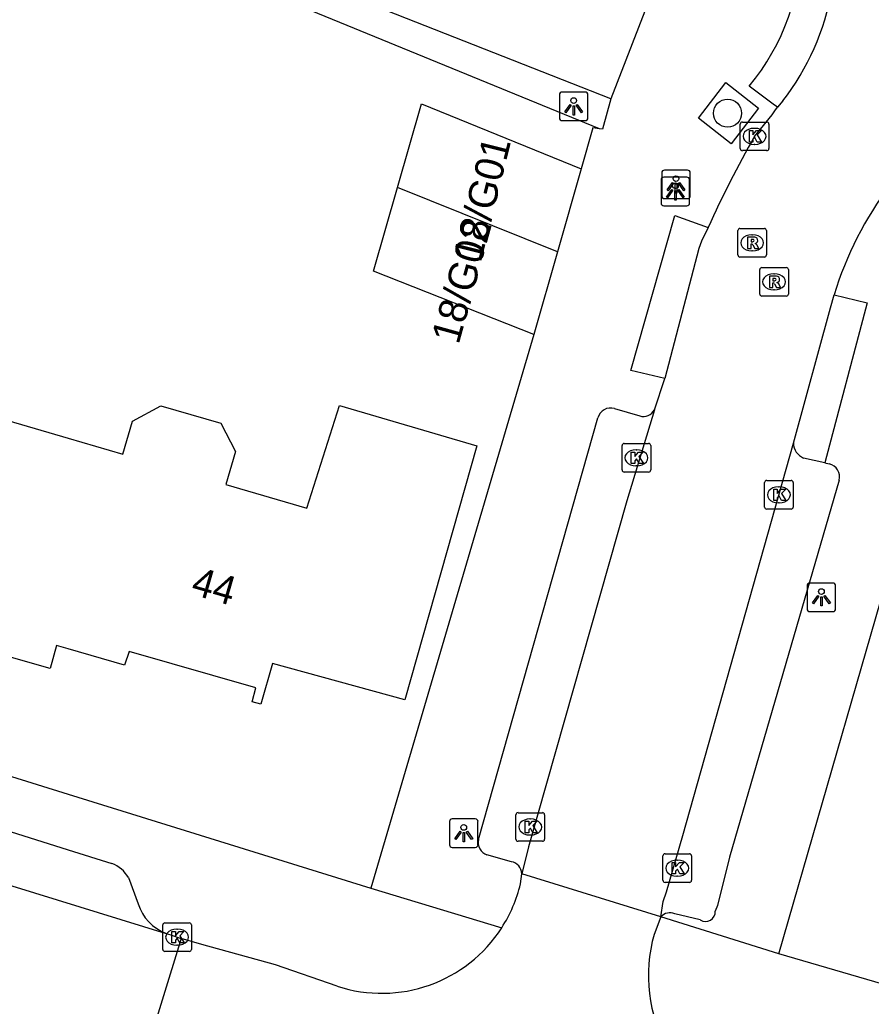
# Model space of a CAD drawing. Extents: x 159718 to 160783, y 383290 to 384030.
# Drawn here: x 159998.31 to 160028.05, y 383507.63 to 383542.1 of the extents above; entities that cross this region are included whole.
import ezdxf

# ---------------------------------------------------------------- set-up
doc = ezdxf.new("R2010")
doc.units = 0
for name, color, linetype in [('IMGEO_Boom', 7, 'Continuous'), ('IMGEO_Hek', 7, 'Continuous'), ('IMGEO_Kolk', 7, 'Continuous'), ('IMGEO_Lichtpunt', 7, 'Continuous'), ('IMGEO_Muur', 7, 'Continuous'), ('IMGEO_Pand', 7, 'Continuous'), ('IMGEO_Pand_nummerreeks', 7, 'Continuous'), ('IMGEO_Parkeervlak_open', 7, 'Continuous'), ('IMGEO_Rijbaan_lokaal_open', 7, 'Continuous'), ('IMGEO_Rioolput', 7, 'Continuous'), ('IMGEO_Voetpad_open', 7, 'Continuous')]:
    doc.layers.add(name, color=color, linetype=linetype)

msp = doc.modelspace()

# ---------------------------------------------------------------- linework, layer by layer
at = {"layer": 'IMGEO_Boom'}
msp.add_circle((160023.032, 383538.831), 0.489, dxfattribs=at)
at = {"layer": 'IMGEO_Hek'}
msp.add_lwpolyline([(160018.559, 383538.287), (160004.082, 383544.224), (160006.109, 383549.395), (160000, 383551.763)], dxfattribs=at)
at = {"layer": 'IMGEO_Kolk'}
for p, q in [((160023.475, 383537.597), (160023.475, 383538.449)), ((160023.55, 383538.523), (160024.402, 383538.523)), ((160024.476, 383538.449), (160024.476, 383537.597)), ((160023.963, 383538.303), (160023.988, 383538.303)), ((160024.402, 383537.523), (160023.55, 383537.523)), ((160023.986, 383537.743), (160023.961, 383537.743)), ((160019.347, 383526.368), (160019.347, 383527.22)), ((160019.422, 383527.294), (160020.274, 383527.294)), ((160020.348, 383527.22), (160020.348, 383526.368)), ((160019.835, 383527.074), (160019.86, 383527.074)), ((160019.858, 383526.514), (160019.833, 383526.514)), ((160020.274, 383526.294), (160019.422, 383526.294)), ((160024.325, 383525.074), (160024.325, 383525.926)), ((160024.4, 383526), (160025.252, 383526)), ((160024.813, 383525.78), (160024.838, 383525.78)), ((160025.326, 383525.926), (160025.326, 383525.074)), ((160024.836, 383525.22), (160024.811, 383525.22)), ((160025.252, 383525), (160024.4, 383525)), ((160015.716, 383514.395), (160016.568, 383514.395)), ((160015.641, 383513.469), (160015.641, 383514.321)), ((160016.129, 383514.175), (160016.154, 383514.175)), ((160016.642, 383514.321), (160016.642, 383513.469)), ((160016.568, 383513.395), (160015.716, 383513.395)), ((160016.152, 383513.615), (160016.127, 383513.615)), ((160020.85, 383512.958), (160021.702, 383512.958)), ((160020.775, 383512.032), (160020.775, 383512.884)), ((160021.263, 383512.738), (160021.288, 383512.738)), ((160021.776, 383512.884), (160021.776, 383512.032)), ((160021.702, 383511.958), (160020.85, 383511.958)), ((160021.286, 383512.178), (160021.261, 383512.178)), ((160003.379, 383510.546), (160004.231, 383510.546)), ((160003.304, 383509.62), (160003.304, 383510.472)), ((160003.792, 383510.326), (160003.817, 383510.326)), ((160004.305, 383510.472), (160004.305, 383509.62)), ((160004.231, 383509.546), (160003.379, 383509.546)), ((160003.815, 383509.766), (160003.79, 383509.766))]:
    msp.add_line(p, q, dxfattribs=at)
for points in [[(160023.475, 383537.597), (160023.475, 383538.449)], [(160023.55, 383538.523), (160024.402, 383538.523)], [(160024.476, 383538.449), (160024.476, 383537.597)], [(160023.796, 383538.223), (160023.919, 383538.223), (160023.919, 383538.072), (160024.049, 383538.223), (160024.213, 383538.223), (160024.067, 383538.072), (160024.22, 383537.823), (160024.068, 383537.823), (160023.983, 383537.987), (160023.919, 383537.92), (160023.919, 383537.823), (160023.796, 383537.823), (160023.796, 383538.223)], [(160024.402, 383537.523), (160023.55, 383537.523)], [(160019.347, 383526.368), (160019.347, 383527.22)], [(160019.422, 383527.294), (160020.274, 383527.294)], [(160020.348, 383527.22), (160020.348, 383526.368)], [(160019.668, 383526.994), (160019.791, 383526.994), (160019.791, 383526.843), (160019.921, 383526.994), (160020.085, 383526.994), (160019.939, 383526.843), (160020.092, 383526.594), (160019.94, 383526.594), (160019.855, 383526.758), (160019.791, 383526.691), (160019.791, 383526.594), (160019.668, 383526.594), (160019.668, 383526.994)], [(160020.274, 383526.294), (160019.422, 383526.294)], [(160024.325, 383525.074), (160024.325, 383525.926)], [(160024.4, 383526), (160025.252, 383526)], [(160024.646, 383525.7), (160024.769, 383525.7), (160024.769, 383525.549), (160024.899, 383525.7), (160025.063, 383525.7), (160024.917, 383525.549), (160025.07, 383525.3), (160024.918, 383525.3), (160024.833, 383525.464), (160024.769, 383525.397), (160024.769, 383525.3), (160024.646, 383525.3), (160024.646, 383525.7)], [(160025.326, 383525.926), (160025.326, 383525.074)], [(160025.252, 383525), (160024.4, 383525)], [(160015.716, 383514.395), (160016.568, 383514.395)], [(160015.641, 383513.469), (160015.641, 383514.321)], [(160015.962, 383514.095), (160016.085, 383514.095), (160016.085, 383513.944), (160016.215, 383514.095), (160016.379, 383514.095), (160016.233, 383513.944), (160016.386, 383513.695), (160016.234, 383513.695), (160016.149, 383513.859), (160016.085, 383513.792), (160016.085, 383513.695), (160015.962, 383513.695), (160015.962, 383514.095)], [(160016.642, 383514.321), (160016.642, 383513.469)], [(160016.568, 383513.395), (160015.716, 383513.395)], [(160020.85, 383512.958), (160021.702, 383512.958)], [(160020.775, 383512.032), (160020.775, 383512.884)], [(160021.096, 383512.658), (160021.219, 383512.658), (160021.219, 383512.507), (160021.349, 383512.658), (160021.513, 383512.658), (160021.367, 383512.507), (160021.52, 383512.258), (160021.368, 383512.258), (160021.283, 383512.422), (160021.219, 383512.355), (160021.219, 383512.258), (160021.096, 383512.258), (160021.096, 383512.658)], [(160021.776, 383512.884), (160021.776, 383512.032)], [(160021.702, 383511.958), (160020.85, 383511.958)], [(160003.379, 383510.546), (160004.231, 383510.546)], [(160003.304, 383509.62), (160003.304, 383510.472)], [(160003.625, 383510.246), (160003.748, 383510.246), (160003.748, 383510.095), (160003.878, 383510.246), (160004.042, 383510.246), (160003.896, 383510.095), (160004.049, 383509.846), (160003.897, 383509.846), (160003.812, 383510.01), (160003.748, 383509.943), (160003.748, 383509.846), (160003.625, 383509.846), (160003.625, 383510.246)], [(160004.305, 383510.472), (160004.305, 383509.62)], [(160004.231, 383509.546), (160003.379, 383509.546)]]:
    msp.add_lwpolyline(points, dxfattribs=at)
for centre, start, end in [((160023.552, 383538.447), 91.552, 178.448), ((160023.552, 383538.447), 91.552, 178.448), ((160024.4, 383538.447), 1.552, 88.448), ((160024.4, 383538.447), 1.552, 88.448), ((160023.552, 383537.599), 181.552, 268.448), ((160023.552, 383537.599), 181.552, 268.448), ((160024.4, 383537.599), 271.552, 358.448), ((160024.4, 383537.599), 271.552, 358.448), ((160019.424, 383527.218), 91.552, 178.448), ((160019.424, 383527.218), 91.552, 178.448), ((160020.272, 383527.218), 1.552, 88.448), ((160020.272, 383527.218), 1.552, 88.448), ((160019.424, 383526.37), 181.552, 268.448), ((160019.424, 383526.37), 181.552, 268.448), ((160020.272, 383526.37), 271.552, 358.448), ((160020.272, 383526.37), 271.552, 358.448), ((160024.402, 383525.924), 91.552, 178.448), ((160024.402, 383525.924), 91.552, 178.448), ((160025.25, 383525.924), 1.552, 88.448), ((160025.25, 383525.924), 1.552, 88.448), ((160024.402, 383525.076), 181.552, 268.448), ((160024.402, 383525.076), 181.552, 268.448), ((160025.25, 383525.076), 271.552, 358.448), ((160025.25, 383525.076), 271.552, 358.448), ((160015.718, 383514.319), 91.552, 178.448), ((160015.718, 383514.319), 91.552, 178.448), ((160016.566, 383514.319), 1.552, 88.448), ((160016.566, 383514.319), 1.552, 88.448), ((160015.718, 383513.471), 181.552, 268.448), ((160015.718, 383513.471), 181.552, 268.448), ((160016.566, 383513.471), 271.552, 358.448), ((160016.566, 383513.471), 271.552, 358.448), ((160020.852, 383512.882), 91.552, 178.448), ((160020.852, 383512.882), 91.552, 178.448), ((160021.7, 383512.882), 1.552, 88.448), ((160021.7, 383512.882), 1.552, 88.448), ((160020.852, 383512.034), 181.552, 268.448), ((160020.852, 383512.034), 181.552, 268.448), ((160021.7, 383512.034), 271.552, 358.448), ((160021.7, 383512.034), 271.552, 358.448), ((160003.381, 383510.47), 91.552, 178.448), ((160003.381, 383510.47), 91.552, 178.448), ((160004.229, 383510.47), 1.552, 88.448), ((160004.229, 383510.47), 1.552, 88.448), ((160003.381, 383509.622), 181.552, 268.448), ((160003.381, 383509.622), 181.552, 268.448), ((160004.229, 383509.622), 271.552, 358.448), ((160004.229, 383509.622), 271.552, 358.448)]:
    msp.add_arc(centre, 0.0765, start, end, dxfattribs=at)
for centre, major_axis, ratio, start_param, end_param in [((160023.962, 383538.023), (-0.387, 0.002), 0.722429, 4.712389, 7.853982), ((160023.987, 383538.023), (-0.39, 0.002), 0.717154, 1.570796, 4.712389), ((160019.834, 383526.794), (-0.387, 0.002), 0.722429, 4.712389, 7.853982), ((160019.859, 383526.794), (-0.39, 0.002), 0.717154, 1.570796, 4.712389), ((160024.812, 383525.5), (-0.387, 0.002), 0.722429, 4.712389, 7.853982), ((160024.837, 383525.5), (-0.39, 0.002), 0.717154, 1.570796, 4.712389), ((160016.128, 383513.895), (-0.387, 0.002), 0.722429, 4.712389, 7.853982), ((160016.153, 383513.895), (-0.39, 0.002), 0.717154, 1.570796, 4.712389), ((160021.262, 383512.458), (-0.387, 0.002), 0.722429, 4.712389, 7.853982), ((160021.287, 383512.458), (-0.39, 0.002), 0.717154, 1.570796, 4.712389), ((160003.791, 383510.046), (-0.387, 0.002), 0.722429, 4.712389, 7.853982), ((160003.816, 383510.046), (-0.39, 0.002), 0.717154, 1.570796, 4.712389)]:
    msp.add_ellipse(centre, major_axis=major_axis, ratio=ratio, start_param=start_param, end_param=end_param, dxfattribs=at)
at = {"layer": 'IMGEO_Lichtpunt'}
for p, q in [((160018.06, 383539.569), (160017.252, 383539.569)), ((160018.06, 383539.569), (160017.252, 383539.569)), ((160017.158, 383539.474), (160017.158, 383538.667)), ((160017.158, 383539.474), (160017.158, 383538.667)), ((160018.154, 383538.667), (160018.154, 383539.474)), ((160018.154, 383538.667), (160018.154, 383539.474)), ((160017.252, 383538.573), (160018.06, 383538.573)), ((160017.252, 383538.573), (160018.06, 383538.573)), ((160020.732, 383536.748), (160020.732, 383535.941)), ((160020.732, 383536.748), (160020.732, 383535.941)), ((160021.634, 383536.843), (160020.826, 383536.843)), ((160021.634, 383536.843), (160020.826, 383536.843)), ((160021.728, 383535.941), (160021.728, 383536.748)), ((160021.728, 383535.941), (160021.728, 383536.748)), ((160020.711, 383536.502), (160020.711, 383535.695)), ((160020.711, 383536.502), (160020.711, 383535.695)), ((160021.613, 383536.597), (160020.805, 383536.597)), ((160021.613, 383536.597), (160020.805, 383536.597)), ((160021.707, 383535.695), (160021.707, 383536.502)), ((160021.707, 383535.695), (160021.707, 383536.502)), ((160020.826, 383535.847), (160021.634, 383535.847)), ((160020.826, 383535.847), (160021.634, 383535.847)), ((160020.805, 383535.601), (160021.613, 383535.601)), ((160020.805, 383535.601), (160021.613, 383535.601)), ((160025.812, 383522.322), (160025.812, 383521.515)), ((160025.812, 383522.322), (160025.812, 383521.515)), ((160026.714, 383522.417), (160025.906, 383522.417)), ((160026.714, 383522.417), (160025.906, 383522.417)), ((160026.808, 383521.515), (160026.808, 383522.322)), ((160026.808, 383521.515), (160026.808, 383522.322)), ((160025.906, 383521.421), (160026.714, 383521.421)), ((160025.906, 383521.421), (160026.714, 383521.421)), ((160013.319, 383514.083), (160013.319, 383513.276)), ((160013.319, 383514.083), (160013.319, 383513.276)), ((160014.221, 383514.178), (160013.413, 383514.178)), ((160014.221, 383514.178), (160013.413, 383514.178)), ((160014.315, 383513.276), (160014.315, 383514.083)), ((160014.315, 383513.276), (160014.315, 383514.083)), ((160013.413, 383513.182), (160014.221, 383513.182)), ((160013.413, 383513.182), (160014.221, 383513.182))]:
    msp.add_line(p, q, dxfattribs=at)
for points in [[(160017.532, 383539.138), (160017.571, 383539.11), (160017.383, 383538.848), (160017.345, 383538.875), (160017.532, 383539.138)], [(160017.744, 383539.11), (160017.782, 383539.137), (160017.969, 383538.875), (160017.93, 383538.847), (160017.744, 383539.11)], [(160017.634, 383539.09), (160017.681, 383539.09), (160017.681, 383538.768), (160017.634, 383538.768), (160017.634, 383539.09)], [(160021.106, 383536.412), (160021.145, 383536.384), (160020.957, 383536.122), (160020.919, 383536.149), (160021.106, 383536.412)], [(160021.318, 383536.384), (160021.356, 383536.411), (160021.543, 383536.149), (160021.504, 383536.121), (160021.318, 383536.384)], [(160021.085, 383536.166), (160021.124, 383536.138), (160020.936, 383535.876), (160020.898, 383535.903), (160021.085, 383536.166)], [(160021.187, 383536.118), (160021.234, 383536.118), (160021.234, 383535.796), (160021.187, 383535.796), (160021.187, 383536.118)], [(160021.208, 383536.364), (160021.255, 383536.364), (160021.255, 383536.042), (160021.208, 383536.042), (160021.208, 383536.364)], [(160021.297, 383536.138), (160021.335, 383536.165), (160021.522, 383535.903), (160021.483, 383535.875), (160021.297, 383536.138)], [(160026.186, 383521.986), (160026.225, 383521.958), (160026.037, 383521.696), (160025.999, 383521.723), (160026.186, 383521.986)], [(160026.288, 383521.938), (160026.335, 383521.938), (160026.335, 383521.616), (160026.288, 383521.616), (160026.288, 383521.938)], [(160026.398, 383521.958), (160026.436, 383521.985), (160026.623, 383521.723), (160026.584, 383521.695), (160026.398, 383521.958)], [(160013.693, 383513.747), (160013.732, 383513.719), (160013.544, 383513.457), (160013.506, 383513.484), (160013.693, 383513.747)], [(160013.795, 383513.699), (160013.842, 383513.699), (160013.842, 383513.377), (160013.795, 383513.377), (160013.795, 383513.699)], [(160013.905, 383513.719), (160013.943, 383513.746), (160014.13, 383513.484), (160014.091, 383513.456), (160013.905, 383513.719)]]:
    msp.add_lwpolyline(points, dxfattribs=at)
for centre in [(160017.657, 383539.272), (160021.21, 383536.3), (160021.231, 383536.546), (160026.311, 383522.12), (160013.818, 383513.881)]:
    msp.add_circle(centre, 0.0994, dxfattribs=at)
for centre, start, end in [((160017.252, 383539.474), 90, 180), ((160017.252, 383539.474), 90, 180), ((160018.06, 383539.474), 0, 90), ((160018.06, 383539.474), 0, 90), ((160017.252, 383538.667), 180, 270), ((160017.252, 383538.667), 180, 270), ((160018.06, 383538.667), 270, 0), ((160018.06, 383538.667), 270, 360), ((160020.826, 383536.748), 90, 180), ((160020.826, 383536.748), 90, 180), ((160021.634, 383536.748), 0, 90), ((160021.634, 383536.748), 0, 90), ((160020.805, 383536.502), 90, 180), ((160020.805, 383536.502), 90, 180), ((160021.613, 383536.502), 0, 90), ((160021.613, 383536.502), 0, 90), ((160020.805, 383535.695), 180, 270), ((160020.805, 383535.695), 180, 270), ((160020.826, 383535.941), 180, 270), ((160020.826, 383535.941), 180, 270), ((160021.613, 383535.695), 270, 0), ((160021.613, 383535.695), 270, 360), ((160021.634, 383535.941), 270, 0), ((160021.634, 383535.941), 270, 360), ((160025.906, 383522.322), 90, 180), ((160025.906, 383522.322), 90, 180), ((160026.714, 383522.322), 0, 90), ((160026.714, 383522.322), 0, 90), ((160025.906, 383521.515), 180, 270), ((160025.906, 383521.515), 180, 270), ((160026.714, 383521.515), 270, 0), ((160026.714, 383521.515), 270, 360), ((160013.413, 383514.083), 90, 180), ((160013.413, 383514.083), 90, 180), ((160014.221, 383514.083), 0, 90), ((160014.221, 383514.083), 0, 90), ((160013.413, 383513.276), 180, 270), ((160013.413, 383513.276), 180, 270), ((160014.221, 383513.276), 270, 0), ((160014.221, 383513.276), 270, 360)]:
    msp.add_arc(centre, 0.0946, start, end, dxfattribs=at)
at = {"layer": 'IMGEO_Muur'}
msp.add_lwpolyline([(160016.26, 383531.095), (160014.141, 383523.9)], dxfattribs=at)
at = {"layer": 'IMGEO_Pand'}
for points in [[(160011.505, 383536.235), (160012.342, 383539.155), (160017.916, 383536.885)], [(160017.916, 383536.885), (160017.088, 383533.99)], [(160016.26, 383531.095), (160010.668, 383533.315), (160011.505, 383536.235)], [(160017.088, 383533.99), (160011.505, 383536.235)], [(160017.088, 383533.99), (160016.26, 383531.095)], [(159997.887, 383528.092), (160000, 383527.474), (160001.909, 383526.916), (160002.246, 383528.068), (160003.238, 383528.611), (160005.33, 383528), (160005.845, 383527.016), (160005.508, 383525.864), (160008.339, 383525.036), (160009.479, 383528.619), (160014.278, 383527.216), (160011.757, 383518.334), (160007.138, 383519.604), (160006.734, 383518.188), (160006.431, 383518.272), (160006.552, 383518.751), (160002.13, 383520.03), (160001.97, 383519.55), (160000, 383520.117), (159999.588, 383520.236), (159999.365, 383519.432), (159996.662, 383520.205)]]:
    msp.add_lwpolyline(points, dxfattribs=at)
at = {"layer": 'IMGEO_Parkeervlak_open'}
msp.add_lwpolyline([(160018.952, 383539.329), (160005.658, 383544.572), (160007.458, 383549.351)], dxfattribs=at)
at = {"layer": 'IMGEO_Rijbaan_lokaal_open'}
for points in [[(160024.96, 383539.263), (160024.78, 383539.039)], [(160022.353, 383534.838), (160022.118, 383534.361), (160022.031, 383534.104), (160020.839, 383529.561)], [(160025.336, 383527.308), (160026.627, 383532.035), (160026.754, 383532.484)], [(160020.481, 383528.471), (160020.839, 383529.561)], [(160020.481, 383528.471), (160019.512, 383525.286), (160016.083, 383513.205), (160015.842, 383512.26)], [(160020.706, 383510.759), (160020.788, 383511.29), (160020.904, 383511.625), (160021.468, 383513.596), (160025.336, 383527.308)], [(159991.835, 383513.751), (160003.42, 383510.177)], [(160015.797, 383511.905), (160015.842, 383512.26)], [(160020.706, 383510.759), (160015.842, 383512.26)], [(160020.706, 383510.759), (160020.471, 383510.144)], [(160003.952, 383510.001), (160002.575, 383505.538)], [(160003.42, 383510.177), (160003.587, 383510.126), (160003.802, 383510.046), (160003.952, 383510.001)], [(160009.395, 383508.336), (160007.241, 383509.083), (160004.672, 383509.787), (160003.952, 383510.001)]]:
    msp.add_lwpolyline(points, dxfattribs=at)
for centre, radius, start, end in [((160018.026, 383544.652), 8.782, 322.1453, 350.0506), ((160010.005, 383549.905), 18.34, 319.6198, 323.6683), ((160058.421, 383518.465), 39.61, 150.4114, 155.5839), ((160038.815, 383528.78), 12.617, 143.2996, 162.9268), ((160010.978, 383513.057), 4.955, 327.2232, 346.5515), ((160010.954, 383513.064), 4.979, 251.7512, 327.305), ((160025.427, 383508.699), 5.162, 163.7404, 256.459)]:
    msp.add_arc(centre, radius, start, end, dxfattribs=at)
at = {"layer": 'IMGEO_Rioolput'}
for p, q in [((160023.391, 383533.878), (160023.391, 383534.73)), ((160023.466, 383534.804), (160024.318, 383534.804)), ((160024.392, 383534.73), (160024.392, 383533.878)), ((160023.879, 383534.584), (160023.904, 383534.584)), ((160023.902, 383534.024), (160023.877, 383534.024)), ((160024.318, 383533.804), (160023.466, 383533.804)), ((160024.156, 383532.514), (160024.156, 383533.366)), ((160024.231, 383533.44), (160025.083, 383533.44)), ((160025.157, 383533.366), (160025.157, 383532.514)), ((160024.644, 383533.22), (160024.669, 383533.22)), ((160024.667, 383532.66), (160024.642, 383532.66)), ((160025.083, 383532.44), (160024.231, 383532.44))]:
    msp.add_line(p, q, dxfattribs=at)
for points in [[(160023.391, 383533.878), (160023.391, 383534.73)], [(160023.466, 383534.804), (160024.318, 383534.804)], [(160024.392, 383534.73), (160024.392, 383533.878)], [(160023.98, 383534.502), (160023.728, 383534.504), (160023.728, 383534.104)], [(160023.906, 383534.423), (160023.852, 383534.423), (160023.852, 383534.342)], [(160023.852, 383534.342), (160023.904, 383534.342)], [(160023.728, 383534.104), (160023.852, 383534.104), (160023.852, 383534.266), (160023.863, 383534.266)], [(160023.91, 383534.237), (160023.981, 383534.104), (160024.121, 383534.104), (160024.056, 383534.23)], [(160024.318, 383533.804), (160023.466, 383533.804)], [(160024.156, 383532.514), (160024.156, 383533.366)], [(160024.231, 383533.44), (160025.083, 383533.44)], [(160025.157, 383533.366), (160025.157, 383532.514)], [(160024.745, 383533.138), (160024.493, 383533.14), (160024.493, 383532.74)], [(160024.671, 383533.059), (160024.617, 383533.059), (160024.617, 383532.978)], [(160024.617, 383532.978), (160024.669, 383532.978)], [(160024.493, 383532.74), (160024.617, 383532.74), (160024.617, 383532.902), (160024.628, 383532.902)], [(160024.675, 383532.873), (160024.746, 383532.74), (160024.886, 383532.74), (160024.821, 383532.866)], [(160025.083, 383532.44), (160024.231, 383532.44)]]:
    msp.add_lwpolyline(points, dxfattribs=at)
for centre, radius, start, end in [((160023.468, 383534.728), 0.0765, 91.552, 178.448), ((160023.468, 383534.728), 0.0765, 91.552, 178.448), ((160024.316, 383534.728), 0.0765, 1.552, 88.448), ((160024.316, 383534.728), 0.0765, 1.552, 88.448), ((160023.888, 383534.531), 0.19, 274.7715, 282.9687), ((160023.912, 383534.327), 0.0964, 77.0061, 93.1865), ((160023.926, 383534.384), 0.0378, 276.6634, 79.6772), ((160023.979, 383534.392), 0.109, 350.3612, 89.416), ((160023.977, 383534.392), 0.112, 277.5842, 350.9817), ((160023.862, 383534.213), 0.0533, 26.0293, 88.6989), ((160023.961, 383534.177), 0.108, 29.5134, 73.7905), ((160023.468, 383533.88), 0.0765, 181.552, 268.448), ((160023.468, 383533.88), 0.0765, 181.552, 268.448), ((160024.316, 383533.88), 0.0765, 271.552, 358.448), ((160024.316, 383533.88), 0.0765, 271.552, 358.448), ((160024.233, 383533.364), 0.0765, 91.552, 178.448), ((160024.233, 383533.364), 0.0765, 91.552, 178.448), ((160025.081, 383533.364), 0.0765, 1.552, 88.448), ((160025.081, 383533.364), 0.0765, 1.552, 88.448), ((160024.653, 383533.167), 0.19, 274.7715, 282.9687), ((160024.677, 383532.963), 0.0964, 77.0061, 93.1865), ((160024.691, 383533.02), 0.0378, 276.6634, 79.6772), ((160024.744, 383533.028), 0.109, 350.3612, 89.416), ((160024.742, 383533.028), 0.112, 277.5842, 350.9817), ((160024.627, 383532.849), 0.0533, 26.0293, 88.6989), ((160024.726, 383532.813), 0.108, 29.5134, 73.7905), ((160024.233, 383532.516), 0.0765, 181.552, 268.448), ((160024.233, 383532.516), 0.0765, 181.552, 268.448), ((160025.081, 383532.516), 0.0765, 271.552, 358.448), ((160025.081, 383532.516), 0.0765, 271.552, 358.448)]:
    msp.add_arc(centre, radius, start, end, dxfattribs=at)
for centre, major_axis, ratio, start_param, end_param in [((160023.878, 383534.304), (-0.387, 0.002), 0.722429, 4.712389, 7.853982), ((160023.903, 383534.304), (-0.39, 0.002), 0.717154, 1.570796, 4.712389), ((160024.643, 383532.94), (-0.387, 0.002), 0.722429, 4.712389, 7.853982), ((160024.668, 383532.94), (-0.39, 0.002), 0.717154, 1.570796, 4.712389)]:
    msp.add_ellipse(centre, major_axis=major_axis, ratio=ratio, start_param=start_param, end_param=end_param, dxfattribs=at)
at = {"layer": 'IMGEO_Voetpad_open'}
for points in [[(160020.446, 383543.185), (160018.952, 383539.329)], [(160022.974, 383539.903), (160024.119, 383539.007), (160023.164, 383537.759), (160022.019, 383538.655), (160022.974, 383539.903)], [(160024.78, 383539.039), (160024.63, 383539.151), (160023.788, 383539.78)], [(160018.952, 383539.329), (160018.661, 383538.27), (160018.559, 383538.287), (160018.328, 383538.326), (160017.916, 383536.885)], [(160020.839, 383529.561), (160019.649, 383529.837), (160021.19, 383535.256), (160022.353, 383534.838)], [(160026.754, 383532.484), (160027.912, 383532.209), (160026.427, 383526.613)], [(160016.26, 383531.095), (160014.141, 383523.9), (160010.566, 383511.76)], [(160024.822, 383509.46), (160030.923, 383530.606)], [(160019.083, 383528.514), (160019.968, 383528.255)], [(160014.334, 383513.463), (160018.506, 383528.184)], [(159962.86, 383526.945), (159989.51, 383518.246), (159992.408, 383517.402), (160000, 383515.043), (160010.566, 383511.76)], [(160026.427, 383526.613), (160025.689, 383526.785)], [(160026.427, 383526.613), (160026.582, 383526.577)], [(160026.931, 383526.01), (160023.099, 383512.839), (160022.676, 383511.152), (160022.603, 383510.956)], [(159993.227, 383513.976), (159994.085, 383514.577), (159994.372, 383514.669), (159994.826, 383514.725), (160000, 383513.101), (160001.525, 383512.622)], [(160015.483, 383512.683), (160014.629, 383512.924)], [(160002.107, 383512.127), (160002.444, 383511.205)], [(160010.566, 383511.76), (160015.144, 383510.375)], [(160024.822, 383509.46), (160020.706, 383510.759)], [(160022.079, 383510.647), (160021.19, 383510.862)], [(160052.735, 383501.318), (160024.822, 383509.46)]]:
    msp.add_lwpolyline(points, dxfattribs=at)
for centre, radius, start, end in [((160017.723, 383544.838), 7.898, 320.1744, 0.5066), ((160018.948, 383528.08), 0.454, 72.7674, 166.7651), ((160020.09, 383528.682), 0.445, 254.0749, 331.5924), ((160025.891, 383527.302), 0.555, 179.3807, 248.6543), ((160026.485, 383526.126), 0.461, 345.3858, 77.8405), ((160014.774, 383513.353), 0.453, 165.991, 251.3936), ((160001.109, 383511.543), 1.156, 30.3297, 68.9069), ((160015.399, 383512.248), 0.443, 1.5284, 79.1141), ((160003.972, 383511.679), 1.6, 197.2241, 249.8031), ((160021.02, 383510.472), 0.426, 66.4895, 137.5383), ((160022.257, 383510.944), 0.347, 239.1531, 1.9021)]:
    msp.add_arc(centre, radius, start, end, dxfattribs=at)

# ---------------------------------------------------------------- texts
at = {"layer": 'IMGEO_Pand_nummerreeks'}
for s, rotation, p in [('18/G01', 75.9638, (160014.407, 383533.584)), ('18/G02', 74.5388, (160013.637, 383530.724)), ('44', 343.8682, (160004.248, 383522.04))]:
    msp.add_text(s, height=1, rotation=rotation, dxfattribs=at).set_placement(p)

doc.saveas('drawing.dxf')
